Omron CX-Programmer project NewProject (CX-Programmer 8.10)

# PLC NewPLC1: CJ1M CPU11
I/O table (CPU CJ1M-CPU11): rack 0 slot 0 CJ1W-ID211; rack 0 slot 1 CJ1W-TC002

## Global symbols (name address type ; comment)
D2000 CHANNEL  ; Loop 1 Current Temperature To Touch Screen
D2001 CHANNEL  ; Loop 2 Current Temperature To Touch Screen
D2002 CHANNEL  ; Loop 3 Current Temperature To Touch Screen
D2003 CHANNEL  ; Loop 4 Current Temperature To Touch Screen
D2100 CHANNEL  ; Loop 1 Temperature Set Point From Touch Screen
D2101 CHANNEL  ; Loop 2 Temperature Set Point From Touch Screen
D2102 CHANNEL  ; Loop 3 Temperature Set Point From Touch Screen
D2103 CHANNEL  ; Loop 4 Temperature Set Point From Touch Screen
W0.00 BOOL  ; Loop 1 Set Point Button
W0.01 BOOL  ; Loop 2 Set Point Button
W0.02 BOOL  ; Loop 3 Set Point Button
W0.03 BOOL  ; Loop 4 Set Point Button
W1.00 BOOL  ; Loop 1 Autotune Start
W1.01 BOOL  ; Loop 2 Autotune Start
W1.02 BOOL  ; Loop 3 Autotune Start
W1.03 BOOL  ; Loop 4 Autotune Start
W2.00 BOOL  ; Loop 1 Autotuning In Progress
W2.01 BOOL  ; Loop 2 Autotuning In Progress
W2.02 BOOL  ; Loop 3 Autotuning In Progress
W2.03 BOOL  ; Loop 4 Autotuning In Progress
Loop1AL1Flag 2008.01 BOOL  ; $?St$Bk?_#[569] / Loop 1 AL1 Flag / The AL1/AL2 Flag is ON when the temperature is within the alarm range set for the input value. / The flag is OFF when the temperature is not within the alarm range set for the input value.$?St$Bk?_#[569]
Loop1AL2Flag 2008.00 BOOL  ; $?St$Bk?_#[570] / Loop 1 AL2 Flag / The AL1/AL2 Flag is ON when the temperature is within the alarm range set for the input value. / The flag is OFF when the temperature is not within the alarm range set for the input value.$?St$Bk?_#[570]
Loop1ATFlag 2008.03 BOOL  ; $?St$Bk?_#[571] / Loop 1 AT Flag / The AT Flag is ON when autotuning is being performed. / The AT Flag is OFF when autotuning is not being performed.$?St$Bk?_#[571]
Loop1ControlOutputFlag 2008.04 BOOL  ; $?St$Bk?_#[575] / Loop 1 Control Output Flag / The Control Output Flag is ON when the control output is ON.$?St$Bk?_#[575]
Loop1InputAlarm1SV D20030 CHANNEL  ; $?St$Bk?_#[577] / Loop 1 Input Alarm 1 SV / The Temperature Control Unit returns the values that are actually being used for temperature control. / Use these values to monitor operation.$?St$Bk?_#[577]
Loop1InputAlarm2SV D20031 CHANNEL  ; $?St$Bk?_#[578] / Loop 1 Input Alarm 2 SV / The Temperature Control Unit returns the values that are actually being used for temperature control. / Use these values to monitor operation.$?St$Bk?_#[578]
Loop1InputControlPeriod D20033 CHANNEL  ; $?St$Bk?_#[579] / Loop 1 Input Control Period / The Temperature Control Unit returns the values that are actually being used for temperature control. / Use these values to monitor operation.$?St$Bk?_#[579]
Loop1InputControlSensitivity D20034 CHANNEL  ; $?St$Bk?_#[580] / Loop 1 Input Control Sensitivity / The Temperature Control Unit returns the values that are actually being used for temperature control. / Use these values to monitor operation.$?St$Bk?_#[580]
Loop1InputDerivativeTime D20037 CHANNEL  ; $?St$Bk?_#[581] / Loop 1 Input Derivative Time / The Temperature Control Unit returns the values that are actually being used for temperature control. / Use these values to monitor operation.$?St$Bk?_#[581]
Loop1InputInputCompensationValue D20032 CHANNEL  ; $?St$Bk?_#[582] / Loop 1 Input Input Compensation Value / The Temperature Control Unit returns the values that are actually being used for temperature control. / Use these values to monitor operation.$?St$Bk?_#[582]
Loop1InputIntegralTime D20036 CHANNEL  ; $?St$Bk?_#[583] / Loop 1 Input Integral Time / The Temperature Control Unit returns the values that are actually being used for temperature control. / Use these values to monitor operation.$?St$Bk?_#[583]
Loop1InputProportionalBand D20035 CHANNEL  ; $?St$Bk?_#[585] / Loop 1 Input Proportional Band / The Temperature Control Unit returns the values that are actually being used for temperature control. / Use these values to monitor operation.$?St$Bk?_#[585]
Loop1OutputControlPeriod D20013 CHANNEL  ; $?St$Bk?_#[589] / Loop 1 Output Control Period / Set in 4-digit BCD or 16-bit binary. / The values written here are written to RAM.$?St$Bk?_#[589]
Loop1OutputControlSensitivity D20014 CHANNEL  ; $?St$Bk?_#[590] / Loop 1 Output Control Sensitivity / Set in 4-digit BCD or 16-bit binary. / The values written here are written to RAM. / This setting is valid with ON/OFF control only.$?St$Bk?_#[590]
Loop1OutputDerivativeTime D20017 CHANNEL  ; $?St$Bk?_#[591] / Loop 1 Output Derivative Time / Set in 4-digit BCD or 16-bit binary. / The values written here are not written to RAM while the PID Constants Calculated Flag is ON. / The values written here are written to RAM. / These settings are valid with PID control only$?St$Bk?_#[591]
Loop1OutputIntegralTime D20016 CHANNEL  ; $?St$Bk?_#[593] / Loop 1 Output Integral Time / Set in 4-digit BCD or 16-bit binary. / The values written here are not written to RAM while the PID Constants Calculated Flag is ON. / The values written here are written to RAM. / These settings are valid with PID control only$?St$Bk?_#[593]
Loop1OutputProportionalBand D20015 CHANNEL  ; $?St$Bk?_#[594] / Loop 1 Output Proportional Band / Set in 4-digit BCD or 16-bit binary. / The values written here are not written to RAM while the PID Constants Calculated Flag is ON. / The values written here are written to RAM. / These settings are valid with PID control only$?St$Bk?_#[594]
Loop1SaveBit 2002.15 BOOL  ; $?St$Bk?_#[597] / Loop 1 Save Bit / Operating Parameters are written from RAM to EEPROM in the Temperature Control Unit when a Save Bit is turned ON. Refer to 2-6 Data Ranges for a list of the specific parameters that are / written. / DO NOT turn OFF the power supply when data is being written / from RAM to EEPROM. Confirm that the Save Completed Flag / has turned ON before turning OFF the power supply.$?St$Bk?_#[597]
Loop1SensorErrorFlag 2008.14 BOOL  ; $?St$Bk?_#[599] / Loop 1 Sensor Error Flag / The Sensor Error Flag turns ON for the following: / A sensor is not connected. / The connection to sensor is broken. / A temperature exceeding the specified temperature range has been input.$?St$Bk?_#[599]
Loop1SettingErrorFlag 2008.09 BOOL  ; $?St$Bk?_#[602] / Loop 1 Setting Error Flag / The Setting Error Flag turns ON when there is a setting error in the settings in the I/O memory of the CPU Unit.$?St$Bk?_#[602]
Loop1StandbyFlag 2008.11 BOOL  ; $?St$Bk?_#[603] / Loop 1 Standby Flag / The Standby Flag turns ON when the Temperature Control Unit is waiting for I/O refreshing after power is turned ON or the Unit is restarted.$?St$Bk?_#[603]
Loop1StartATBit 2002.02 BOOL  ; $?St$Bk?_#[604] / Loop 1 Start AT Bit / Turn ON the Start AT Bit to start autotuning for loop 1. / The status / of the Stop AT Bit is ignored if the Stop AT Bit for loop 1 is ON.$?St$Bk?_#[604]
Loop1StopATBit 2002.03 BOOL  ; $?St$Bk?_#[605] / Loop 1 Stop AT Bit / Turn ON the Stop AT Bit to stop autotuning for loop 1. / The status of the Stop AT Bit is ignored if autotuning is not being performed.$?St$Bk?_#[605]
Loop1StopBit 2002.06 BOOL  ; $?St$Bk?_#[606] / Loop 1 Stop Bit / Turn OFF the Stop Bit to perform temperature control for loop 1 and turn it ON to stop temperature control for loop 1. / The Stop Bit will not function if pin 1 on the DIP switch is OFF and the CPU Unit is in PROGRAM mode.$?St$Bk?_#[606]
Loop2AL1Flag 2009.01 BOOL  ; $?St$Bk?_#[608] / Loop 2 AL1 Flag / The AL1/AL2 Flag is ON when the temperature is within the alarm range set for the input value. / The flag is OFF when the temperature is not within the alarm range set for the input value.$?St$Bk?_#[608]
Loop2AL2Flag 2009.00 BOOL  ; $?St$Bk?_#[609] / Loop 2 AL2 Flag / The AL1/AL2 Flag is ON when the temperature is within the alarm range set for the input value. / The flag is OFF when the temperature is not within the alarm range set for the input value.$?St$Bk?_#[609]
Loop2ATFlag 2009.03 BOOL  ; $?St$Bk?_#[610] / Loop 2 AT Flag / The AT Flag is ON when autotuning is being performed. / The AT Flag is OFF when autotuning is not being performed.$?St$Bk?_#[610]
Loop2ControlOutputFlag 2009.04 BOOL  ; $?St$Bk?_#[614] / Loop 2 Control Output Flag / The Control Output Flag is ON when the control output is ON.$?St$Bk?_#[614]
Loop2InputAlarm1SV D20040 CHANNEL  ; $?St$Bk?_#[616] / Loop 2 Input Alarm 1 SV / The Temperature Control Unit returns the values that are actually being used for temperature control. / Use these values to monitor operation.$?St$Bk?_#[616]
Loop2InputAlarm2SV D20041 CHANNEL  ; $?St$Bk?_#[617] / Loop 2 Input Alarm 2 SV / The Temperature Control Unit returns the values that are actually being used for temperature control. / Use these values to monitor operation.$?St$Bk?_#[617]
Loop2InputControlPeriod D20043 CHANNEL  ; $?St$Bk?_#[618] / Loop 2 Input Control Period / The Temperature Control Unit returns the values that are actually being used for temperature control. / Use these values to monitor operation.$?St$Bk?_#[618]
Loop2InputControlSensitivity D20044 CHANNEL  ; $?St$Bk?_#[619] / Loop 2 Input Control Sensitivity / The Temperature Control Unit returns the values that are actually being used for temperature control. / Use these values to monitor operation.$?St$Bk?_#[619]
Loop2InputDerivativeTime D20047 CHANNEL  ; $?St$Bk?_#[620] / Loop 2 Input Derivative Time / The Temperature Control Unit returns the values that are actually being used for temperature control. / Use these values to monitor operation.$?St$Bk?_#[620]
Loop2InputInputCompensationValue D20042 CHANNEL  ; $?St$Bk?_#[621] / Loop 2 Input Input Compensation Value / The Temperature Control Unit returns the values that are actually being used for temperature control. / Use these values to monitor operation.$?St$Bk?_#[621]
Loop2InputIntegralTime D20046 CHANNEL  ; $?St$Bk?_#[622] / Loop 2 Input Integral Time / The Temperature Control Unit returns the values that are actually being used for temperature control. / Use these values to monitor operation.$?St$Bk?_#[622]
Loop2InputProportionalBand D20045 CHANNEL  ; $?St$Bk?_#[624] / Loop 2 Input Proportional Band / The Temperature Control Unit returns the values that are actually being used for temperature control. / Use these values to monitor operation.$?St$Bk?_#[624]
Loop2OutputControlPeriod D20023 CHANNEL  ; $?St$Bk?_#[627] / Loop 2 Output Control Period / Set in 4-digit BCD or 16-bit binary. / The values written here are written to RAM.$?St$Bk?_#[627]
Loop2OutputControlSensitivity D20024 CHANNEL  ; $?St$Bk?_#[628] / Loop 2 Output Control Sensitivity / Set in 4-digit BCD or 16-bit binary. / The values written here are written to RAM. / This setting is valid with ON/OFF control only.$?St$Bk?_#[628]
Loop2OutputDerivativeTime D20027 CHANNEL  ; $?St$Bk?_#[629] / Loop 2 Output Derivative Time / Set in 4-digit BCD or 16-bit binary. / The values written here are not written to RAM while the PID Constants Calculated Flag is ON. / The values written here are written to RAM. / These settings are valid with PID control only$?St$Bk?_#[629]
Loop2OutputIntegralTime D20026 CHANNEL  ; $?St$Bk?_#[631] / Loop 2 Output Integral Time / Set in 4-digit BCD or 16-bit binary. / The values written here are not written to RAM while the PID Constants Calculated Flag is ON. / The values written here are written to RAM. / These settings are valid with PID control only$?St$Bk?_#[631]
Loop2OutputProportionalBand D20025 CHANNEL  ; $?St$Bk?_#[632] / Loop 2 Output Proportional Band / Set in 4-digit BCD or 16-bit binary. / The values written here are not written to RAM while the PID Constants Calculated Flag is ON. / The values written here are written to RAM. / These settings are valid with PID control only$?St$Bk?_#[632]
Loop2SaveBit 2002.14 BOOL  ; $?St$Bk?_#[635] / Loop 2 Save Bit / Operating Parameters are written from RAM to EEPROM in the Temperature Control Unit when a Save Bit is turned ON. Refer to 2-6 Data Ranges for a list of the specific parameters that are / written. / DO NOT turn OFF the power supply when data is being written / from RAM to EEPROM. Confirm that the Save Completed Flag / has turned ON before turning OFF the power supply.$?St$Bk?_#[635]
Loop2SensorErrorFlag 2009.14 BOOL  ; $?St$Bk?_#[637] / Loop 2 Sensor Error Flag / The Sensor Error Flag turns ON for the following: / A sensor is not connected. / The connection to sensor is broken. / A temperature exceeding the specified temperature range has been input.$?St$Bk?_#[637]
Loop2SettingErrorFlag 2009.09 BOOL  ; $?St$Bk?_#[640] / Loop 2 Setting Error Flag / The Setting Error Flag turns ON when there is a setting error in the settings in the I/O memory of the CPU Unit.$?St$Bk?_#[640]
Loop2StandbyFlag 2009.11 BOOL  ; $?St$Bk?_#[641] / Loop 2 Standby Flag / The Standby Flag turns ON when the Temperature Control Unit is waiting for I/O refreshing after power is turned ON or the Unit is restarted.$?St$Bk?_#[641]
Loop2StartATBit 2002.00 BOOL  ; $?St$Bk?_#[642] / Loop 2 Start AT Bit / Turn ON the Start AT Bit to start autotuning for loop 1. / The status / of the Stop AT Bit is ignored if the Stop AT Bit for loop 1 is ON.$?St$Bk?_#[642]
Loop2StopATBit 2002.01 BOOL  ; $?St$Bk?_#[643] / Loop 2 Stop AT Bit / Turn ON the Stop AT Bit to stop autotuning for loop 1. / The status of the Stop AT Bit is ignored if autotuning is not being performed.$?St$Bk?_#[643]
Loop2StopBit 2002.04 BOOL  ; $?St$Bk?_#[644] / Loop 2 Stop Bit / Turn OFF the Stop Bit to perform temperature control for loop 1 and turn it ON to stop temperature control for loop 1. / The Stop Bit will not function if pin 1 on the DIP switch is OFF and the CPU Unit is in PROGRAM mode.$?St$Bk?_#[644]
Loop3AL1Flag 2018.01 BOOL  ; $?St$Bk?_#[646] / Loop 3 AL1 Flag / The AL1/AL2 Flag is ON when the temperature is within the alarm range set for the input value. / The flag is OFF when the temperature is not within the alarm range set for the input value.$?St$Bk?_#[646]
Loop3AL2Flag 2018.00 BOOL  ; $?St$Bk?_#[647] / Loop 3 AL2 Flag / The AL1/AL2 Flag is ON when the temperature is within the alarm range set for the input value. / The flag is OFF when the temperature is not within the alarm range set for the input value.$?St$Bk?_#[647]
Loop3ATFlag 2018.03 BOOL  ; $?St$Bk?_#[648] / Loop 3 AT Flag / The AT Flag is ON when autotuning is being performed. / The AT Flag is OFF when autotuning is not being performed.$?St$Bk?_#[648]
Loop3ControlOutputFlag 2018.04 BOOL  ; $?St$Bk?_#[652] / Loop 3 Control Output Flag / The Control Output Flag is ON when the control output is ON.$?St$Bk?_#[652]
Loop3InputAlarm1SV D20070 CHANNEL  ; $?St$Bk?_#[654] / Loop 3 Input Alarm 1 SV / The Temperature Control Unit returns the values that are actually being used for temperature control. / Use these values to monitor operation.$?St$Bk?_#[654]
Loop3InputAlarm2SV D20071 CHANNEL  ; $?St$Bk?_#[655] / Loop 3 Input Alarm 2 SV / The Temperature Control Unit returns the values that are actually being used for temperature control. / Use these values to monitor operation.$?St$Bk?_#[655]
Loop3InputControlPeriod D20073 CHANNEL  ; $?St$Bk?_#[656] / Loop 3 Input Control Period / The Temperature Control Unit returns the values that are actually being used for temperature control. / Use these values to monitor operation.$?St$Bk?_#[656]
Loop3InputControlSensitivity D20074 CHANNEL  ; $?St$Bk?_#[657] / Loop 3 Input Control Sensitivity / The Temperature Control Unit returns the values that are actually being used for temperature control. / Use these values to monitor operation.$?St$Bk?_#[657]
Loop3InputDerivativeTime D20077 CHANNEL  ; $?St$Bk?_#[658] / Loop 3 Input Derivative Time / The Temperature Control Unit returns the values that are actually being used for temperature control. / Use these values to monitor operation.$?St$Bk?_#[658]
Loop3InputInputCompensationValue D20072 CHANNEL  ; $?St$Bk?_#[659] / Loop 3 Input Input Compensation Value / The Temperature Control Unit returns the values that are actually being used for temperature control. / Use these values to monitor operation.$?St$Bk?_#[659]
Loop3InputIntegralTime D20076 CHANNEL  ; $?St$Bk?_#[660] / Loop 3 Input Integral Time / The Temperature Control Unit returns the values that are actually being used for temperature control. / Use these values to monitor operation.$?St$Bk?_#[660]
Loop3InputProportionalBand D20075 CHANNEL  ; $?St$Bk?_#[662] / Loop 3 Input Proportional Band / The Temperature Control Unit returns the values that are actually being used for temperature control. / Use these values to monitor operation.$?St$Bk?_#[662]
Loop3OutputControlPeriod D20053 CHANNEL  ; $?St$Bk?_#[666] / Loop 3 Output Control Period / Set in 4-digit BCD or 16-bit binary. / The values written here are written to RAM.$?St$Bk?_#[666]
Loop3OutputControlSensitivity D20054 CHANNEL  ; $?St$Bk?_#[667] / Loop 3 Output Control Sensitivity / Set in 4-digit BCD or 16-bit binary. / The values written here are written to RAM. / This setting is valid with ON/OFF control only.$?St$Bk?_#[667]
Loop3OutputDerivativeTime D20057 CHANNEL  ; $?St$Bk?_#[668] / Loop 3 Output Derivative Time / Set in 4-digit BCD or 16-bit binary. / The values written here are not written to RAM while the PID Constants Calculated Flag is ON. / The values written here are written to RAM. / These settings are valid with PID control only$?St$Bk?_#[668]
Loop3OutputIntegralTime D20056 CHANNEL  ; $?St$Bk?_#[670] / Loop 3 Output Integral Time / Set in 4-digit BCD or 16-bit binary. / The values written here are not written to RAM while the PID Constants Calculated Flag is ON. / The values written here are written to RAM. / These settings are valid with PID control only$?St$Bk?_#[670]
Loop3OutputProportionalBand D20055 CHANNEL  ; $?St$Bk?_#[671] / Loop 3 Output Proportional Band / Set in 4-digit BCD or 16-bit binary. / The values written here are not written to RAM while the PID Constants Calculated Flag is ON. / The values written here are written to RAM. / These settings are valid with PID control only$?St$Bk?_#[671]
Loop3SaveBit 2012.15 BOOL  ; $?St$Bk?_#[674] / Loop 3 Save Bit / Operating Parameters are written from RAM to EEPROM in the Temperature Control Unit when a Save Bit is turned ON. Refer to 2-6 Data Ranges for a list of the specific parameters that are / written. / DO NOT turn OFF the power supply when data is being written / from RAM to EEPROM. Confirm that the Save Completed Flag / has turned ON before turning OFF the power supply.$?St$Bk?_#[674]
Loop3SensorErrorFlag 2018.14 BOOL  ; $?St$Bk?_#[676] / Loop 3 Sensor Error Flag / The Sensor Error Flag turns ON for the following: / A sensor is not connected. / The connection to sensor is broken. / A temperature exceeding the specified temperature range has been input.$?St$Bk?_#[676]
Loop3SettingErrorFlag 2018.09 BOOL  ; $?St$Bk?_#[679] / Loop 3 Setting Error Flag / The Setting Error Flag turns ON when there is a setting error in the settings in the I/O memory of the CPU Unit.$?St$Bk?_#[679]
Loop3StandbyFlag 2018.11 BOOL  ; $?St$Bk?_#[680] / Loop 3 Standby Flag / The Standby Flag turns ON when the Temperature Control Unit is waiting for I/O refreshing after power is turned ON or the Unit is restarted.$?St$Bk?_#[680]
Loop3StartATBit 2012.02 BOOL  ; $?St$Bk?_#[681] / Loop 3 Start AT Bit / Turn ON the Start AT Bit to start autotuning for Loop 3. / The status / of the Stop AT Bit is ignored if the Stop AT Bit for Loop 3 is ON.$?St$Bk?_#[681]
Loop3StopATBit 2012.03 BOOL  ; $?St$Bk?_#[682] / Loop 3 Stop AT Bit / Turn ON the Stop AT Bit to stop autotuning for Loop 3. / The status of the Stop AT Bit is ignored if autotuning is not being performed.$?St$Bk?_#[682]
Loop3StopBit 2012.06 BOOL  ; $?St$Bk?_#[683] / Loop 3 Stop Bit / Turn OFF the Stop Bit to perform temperature control for Loop 3 and turn it ON to stop temperature control for Loop 3. / The Stop Bit will not function if pin 1 on the DIP switch is OFF and the CPU Unit is in PROGRAM mode.$?St$Bk?_#[683]
Loop4AL1Flag 2019.01 BOOL  ; $?St$Bk?_#[685] / Loop 4 AL1 Flag / The AL1/AL2 Flag is ON when the temperature is within the alarm range set for the input value. / The flag is OFF when the temperature is not within the alarm range set for the input value.$?St$Bk?_#[685]
Loop4AL2Flag 2019.00 BOOL  ; $?St$Bk?_#[686] / Loop 4 AL2 Flag / The AL1/AL2 Flag is ON when the temperature is within the alarm range set for the input value. / The flag is OFF when the temperature is not within the alarm range set for the input value.$?St$Bk?_#[686]
Loop4ATFlag 2019.03 BOOL  ; $?St$Bk?_#[687] / Loop 4 AT Flag / The AT Flag is ON when autotuning is being performed. / The AT Flag is OFF when autotuning is not being performed.$?St$Bk?_#[687]
Loop4ControlOutputFlag 2019.04 BOOL  ; $?St$Bk?_#[691] / Loop 4 Control Output Flag / The Control Output Flag is ON when the control output is ON.$?St$Bk?_#[691]
Loop4InputAlarm1SV D20080 CHANNEL  ; $?St$Bk?_#[693] / Loop 4 Input Alarm 1 SV / The Temperature Control Unit returns the values that are actually being used for temperature control. / Use these values to monitor operation.$?St$Bk?_#[693]
Loop4InputAlarm2SV D20081 CHANNEL  ; $?St$Bk?_#[694] / Loop 4 Input Alarm 2 SV / The Temperature Control Unit returns the values that are actually being used for temperature control. / Use these values to monitor operation.$?St$Bk?_#[694]
Loop4InputControlPeriod D20083 CHANNEL  ; $?St$Bk?_#[695] / Loop 4 Input Control Period / The Temperature Control Unit returns the values that are actually being used for temperature control. / Use these values to monitor operation.$?St$Bk?_#[695]
Loop4InputControlSensitivity D20084 CHANNEL  ; $?St$Bk?_#[696] / Loop 4 Input Control Sensitivity / The Temperature Control Unit returns the values that are actually being used for temperature control. / Use these values to monitor operation.$?St$Bk?_#[696]
Loop4InputDerivativeTime D20087 CHANNEL  ; $?St$Bk?_#[697] / Loop 4 Input Derivative Time / The Temperature Control Unit returns the values that are actually being used for temperature control. / Use these values to monitor operation.$?St$Bk?_#[697]
Loop4InputInputCompensationValue D20082 CHANNEL  ; $?St$Bk?_#[698] / Loop 4 Input Input Compensation Value / The Temperature Control Unit returns the values that are actually being used for temperature control. / Use these values to monitor operation.$?St$Bk?_#[698]
Loop4InputIntegralTime D20086 CHANNEL  ; $?St$Bk?_#[699] / Loop 4 Input Integral Time / The Temperature Control Unit returns the values that are actually being used for temperature control. / Use these values to monitor operation.$?St$Bk?_#[699]
Loop4InputProportionalBand D20085 CHANNEL  ; $?St$Bk?_#[701] / Loop 4 Input Proportional Band / The Temperature Control Unit returns the values that are actually being used for temperature control. / Use these values to monitor operation.$?St$Bk?_#[701]
Loop4OutputControlPeriod D20063 CHANNEL  ; $?St$Bk?_#[704] / Loop 4 Output Control Period / Set in 4-digit BCD or 16-bit binary. / The values written here are written to RAM.$?St$Bk?_#[704]
Loop4OutputControlSensitivity D20064 CHANNEL  ; $?St$Bk?_#[705] / Loop 4 Output Control Sensitivity / Set in 4-digit BCD or 16-bit binary. / The values written here are written to RAM. / This setting is valid with ON/OFF control only.$?St$Bk?_#[705]
Loop4OutputDerivativeTime D20067 CHANNEL  ; $?St$Bk?_#[706] / Loop 4 Output Derivative Time / Set in 4-digit BCD or 16-bit binary. / The values written here are not written to RAM while the PID Constants Calculated Flag is ON. / The values written here are written to RAM. / These settings are valid with PID control only$?St$Bk?_#[706]
Loop4OutputIntegralTime D20066 CHANNEL  ; $?St$Bk?_#[708] / Loop 4 Output Integral Time / Set in 4-digit BCD or 16-bit binary. / The values written here are not written to RAM while the PID Constants Calculated Flag is ON. / The values written here are written to RAM. / These settings are valid with PID control only$?St$Bk?_#[708]
Loop4OutputProportionalBand D20065 CHANNEL  ; $?St$Bk?_#[709] / Loop 4 Output Proportional Band / Set in 4-digit BCD or 16-bit binary. / The values written here are not written to RAM while the PID Constants Calculated Flag is ON. / The values written here are written to RAM. / These settings are valid with PID control only$?St$Bk?_#[709]
Loop4SaveBit 2012.14 BOOL  ; $?St$Bk?_#[712] / Loop 4 Save Bit / Operating Parameters are written from RAM to EEPROM in the Temperature Control Unit when a Save Bit is turned ON. Refer to 2-6 Data Ranges for a list of the specific parameters that are / written. / DO NOT turn OFF the power supply when data is being written / from RAM to EEPROM. Confirm that the Save Completed Flag / has turned ON before turning OFF the power supply.$?St$Bk?_#[712]
Loop4SensorErrorFlag 2019.14 BOOL  ; $?St$Bk?_#[714] / Loop 4 Sensor Error Flag / The Sensor Error Flag turns ON for the following: / A sensor is not connected. / The connection to sensor is broken. / A temperature exceeding the specified temperature range has been input.$?St$Bk?_#[714]
Loop4SettingErrorFlag 2019.09 BOOL  ; $?St$Bk?_#[717] / Loop 4 Setting Error Flag / The Setting Error Flag turns ON when there is a setting error in the settings in the I/O memory of the CPU Unit.$?St$Bk?_#[717]
Loop4StandbyFlag 2019.11 BOOL  ; $?St$Bk?_#[718] / Loop 4 Standby Flag / The Standby Flag turns ON when the Temperature Control Unit is waiting for I/O refreshing after power is turned ON or the Unit is restarted.$?St$Bk?_#[718]
Loop4StartATBit 2012.00 BOOL  ; $?St$Bk?_#[719] / Loop 4 Start AT Bit / Turn ON the Start AT Bit to start autotuning for Loop 3. / The status / of the Stop AT Bit is ignored if the Stop AT Bit for Loop 3 is ON.$?St$Bk?_#[719]
Loop4StopATBit 2012.01 BOOL  ; $?St$Bk?_#[720] / Loop 4 Stop AT Bit / Turn ON the Stop AT Bit to stop autotuning for Loop 3. / The status of the Stop AT Bit is ignored if autotuning is not being performed.$?St$Bk?_#[720]
Loop4StopBit 2012.04 BOOL  ; $?St$Bk?_#[721] / Loop 4 Stop Bit / Turn OFF the Stop Bit to perform temperature control for Loop 3 and turn it ON to stop temperature control for Loop 3. / The Stop Bit will not function if pin 1 on the DIP switch is OFF and the CPU Unit is in PROGRAM mode.$?St$Bk?_#[721]

## Program NewProgram1 (cyclic task 0)

### Section ReadData

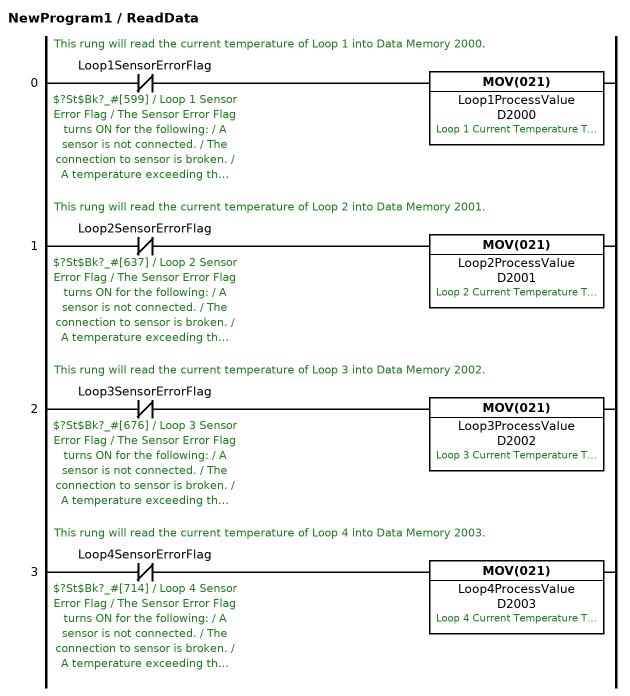
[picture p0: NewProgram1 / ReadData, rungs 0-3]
; rung 0: This rung will read the current temperature of Loop 1 into Data Memory 2000.
LDNOT Loop1SensorErrorFlag  ; $?St$Bk?_#[599] / Loop 1 Sensor Error Flag / The Sensor Error Flag turns ON for the following: / A sensor is not connected. / The connection to sensor is broken. / A temperature exceeding the specified temperature range has been input.$?St$Bk?_#[599]
MOV(021) Loop1ProcessValue D2000  ; Loop 1 Current Temperature To Touch Screen
; rung 1: This rung will read the current temperature of Loop 2 into Data Memory 2001.
LDNOT Loop2SensorErrorFlag  ; $?St$Bk?_#[637] / Loop 2 Sensor Error Flag / The Sensor Error Flag turns ON for the following: / A sensor is not connected. / The connection to sensor is broken. / A temperature exceeding the specified temperature range has been input.$?St$Bk?_#[637]
MOV(021) Loop2ProcessValue D2001  ; Loop 2 Current Temperature To Touch Screen
; rung 2: This rung will read the current temperature of Loop 3 into Data Memory 2002.
LDNOT Loop3SensorErrorFlag  ; $?St$Bk?_#[676] / Loop 3 Sensor Error Flag / The Sensor Error Flag turns ON for the following: / A sensor is not connected. / The connection to sensor is broken. / A temperature exceeding the specified temperature range has been input.$?St$Bk?_#[676]
MOV(021) Loop3ProcessValue D2002  ; Loop 3 Current Temperature To Touch Screen
; rung 3: This rung will read the current temperature of Loop 4 into Data Memory 2003.
LDNOT Loop4SensorErrorFlag  ; $?St$Bk?_#[714] / Loop 4 Sensor Error Flag / The Sensor Error Flag turns ON for the following: / A sensor is not connected. / The connection to sensor is broken. / A temperature exceeding the specified temperature range has been input.$?St$Bk?_#[714]
MOV(021) Loop4ProcessValue D2003  ; Loop 4 Current Temperature To Touch Screen

### Section WriteData

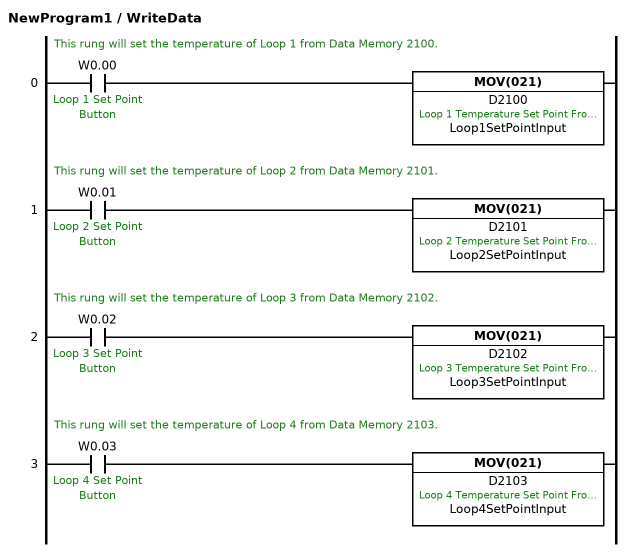
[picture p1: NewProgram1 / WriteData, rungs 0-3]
; rung 0: This rung will set the temperature of Loop 1 from Data Memory 2100.
LD W0.00  ; Loop 1 Set Point Button
MOV(021) D2100 Loop1SetPointInput  ; Loop 1 Temperature Set Point From Touch Screen
; rung 1: This rung will set the temperature of Loop 2 from Data Memory 2101.
LD W0.01  ; Loop 2 Set Point Button
MOV(021) D2101 Loop2SetPointInput  ; Loop 2 Temperature Set Point From Touch Screen
; rung 2: This rung will set the temperature of Loop 3 from Data Memory 2102.
LD W0.02  ; Loop 3 Set Point Button
MOV(021) D2102 Loop3SetPointInput  ; Loop 3 Temperature Set Point From Touch Screen
; rung 3: This rung will set the temperature of Loop 4 from Data Memory 2103.
LD W0.03  ; Loop 4 Set Point Button
MOV(021) D2103 Loop4SetPointInput  ; Loop 4 Temperature Set Point From Touch Screen

### Section Autotune

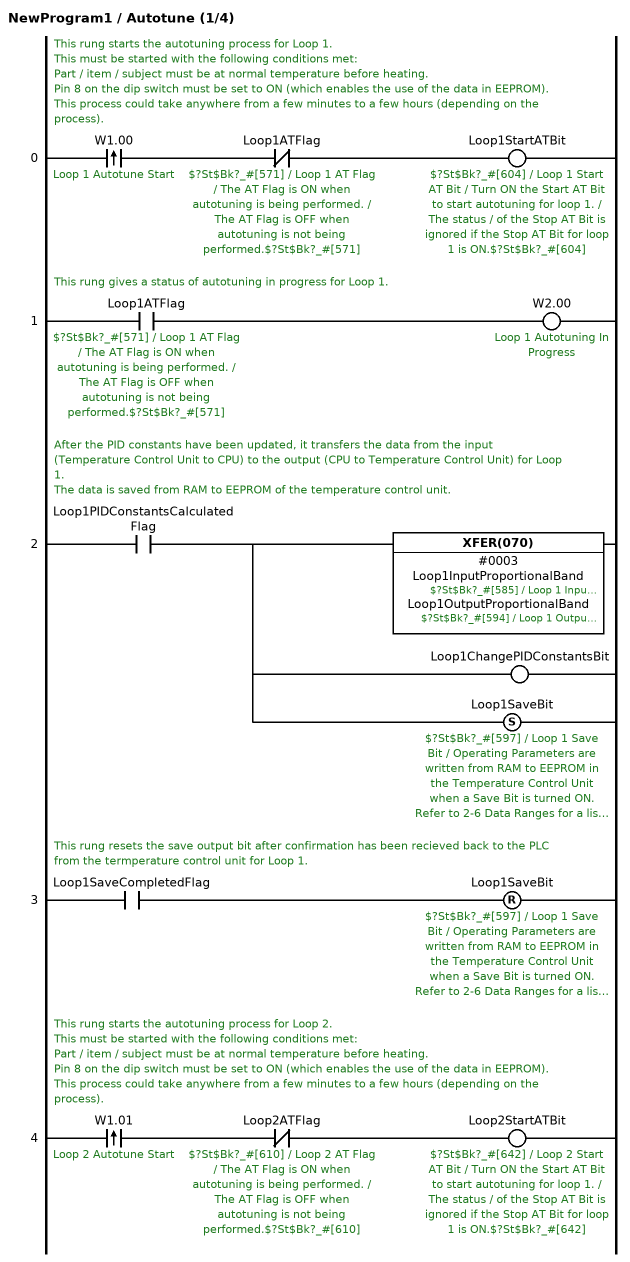
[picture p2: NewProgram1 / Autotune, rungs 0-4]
; rung 0: This rung starts the autotuning process for Loop 1. / This must be started with the following conditions met: / Part / item / subject must be at normal temperature before heating. / Pin 8 on the dip switch must be set to ON (which enables the use of the data in EEPROM). / This process could take anywhere from a few minutes to a few hours (depending on the process).
@LD W1.00  ; Loop 1 Autotune Start
ANDNOT Loop1ATFlag  ; $?St$Bk?_#[571] / Loop 1 AT Flag / The AT Flag is ON when autotuning is being performed. / The AT Flag is OFF when autotuning is not being performed.$?St$Bk?_#[571]
OUT Loop1StartATBit  ; $?St$Bk?_#[604] / Loop 1 Start AT Bit / Turn ON the Start AT Bit to start autotuning for loop 1. / The status / of the Stop AT Bit is ignored if the Stop AT Bit for loop 1 is ON.$?St$Bk?_#[604]
; rung 1: This rung gives a status of autotuning in progress for Loop 1.
LD Loop1ATFlag  ; $?St$Bk?_#[571] / Loop 1 AT Flag / The AT Flag is ON when autotuning is being performed. / The AT Flag is OFF when autotuning is not being performed.$?St$Bk?_#[571]
OUT W2.00  ; Loop 1 Autotuning In Progress
; rung 2: After the PID constants have been updated, it transfers the data from the input (Temperature Control Unit to CPU) to the output (CPU to Temperature Control Unit) for Loop 1. / The data is saved from RAM to EEPROM of the temperature control unit.
LD Loop1PIDConstantsCalculatedFlag
XFER(070) #0003 Loop1InputProportionalBand Loop1OutputProportionalBand  ; $?St$Bk?_#[585] / Loop 1 Input Proportional Band / The Temperature Control Unit returns the values that are actually being used for temperature control. / Use these values to monitor operation.$?St$Bk?_#[585], $?St$Bk?_#[594] / Loop 1 Output Proportional Band / Set in 4-digit BCD or 16-bit binary. / The values written here are not written to RAM while the PID Constants Calculated Flag is ON. / The values written here are written to RAM. / These settings are valid with PID control only$?St$Bk?_#[594]
OUT Loop1ChangePIDConstantsBit
SET Loop1SaveBit  ; $?St$Bk?_#[597] / Loop 1 Save Bit / Operating Parameters are written from RAM to EEPROM in the Temperature Control Unit when a Save Bit is turned ON. Refer to 2-6 Data Ranges for a list of the specific parameters that are / written. / DO NOT turn OFF the power supply when data is being written / from RAM to EEPROM. Confirm that the Save Completed Flag / has turned ON before turning OFF the power supply.$?St$Bk?_#[597]
; rung 3: This rung resets the save output bit after confirmation has been recieved back to the PLC from the termperature control unit for Loop 1.
LD Loop1SaveCompletedFlag
RSET Loop1SaveBit  ; $?St$Bk?_#[597] / Loop 1 Save Bit / Operating Parameters are written from RAM to EEPROM in the Temperature Control Unit when a Save Bit is turned ON. Refer to 2-6 Data Ranges for a list of the specific parameters that are / written. / DO NOT turn OFF the power supply when data is being written / from RAM to EEPROM. Confirm that the Save Completed Flag / has turned ON before turning OFF the power supply.$?St$Bk?_#[597]
; rung 4: This rung starts the autotuning process for Loop 2. / This must be started with the following conditions met: / Part / item / subject must be at normal temperature before heating. / Pin 8 on the dip switch must be set to ON (which enables the use of the data in EEPROM). / This process could take anywhere from a few minutes to a few hours (depending on the process).
@LD W1.01  ; Loop 2 Autotune Start
ANDNOT Loop2ATFlag  ; $?St$Bk?_#[610] / Loop 2 AT Flag / The AT Flag is ON when autotuning is being performed. / The AT Flag is OFF when autotuning is not being performed.$?St$Bk?_#[610]
OUT Loop2StartATBit  ; $?St$Bk?_#[642] / Loop 2 Start AT Bit / Turn ON the Start AT Bit to start autotuning for loop 1. / The status / of the Stop AT Bit is ignored if the Stop AT Bit for loop 1 is ON.$?St$Bk?_#[642]

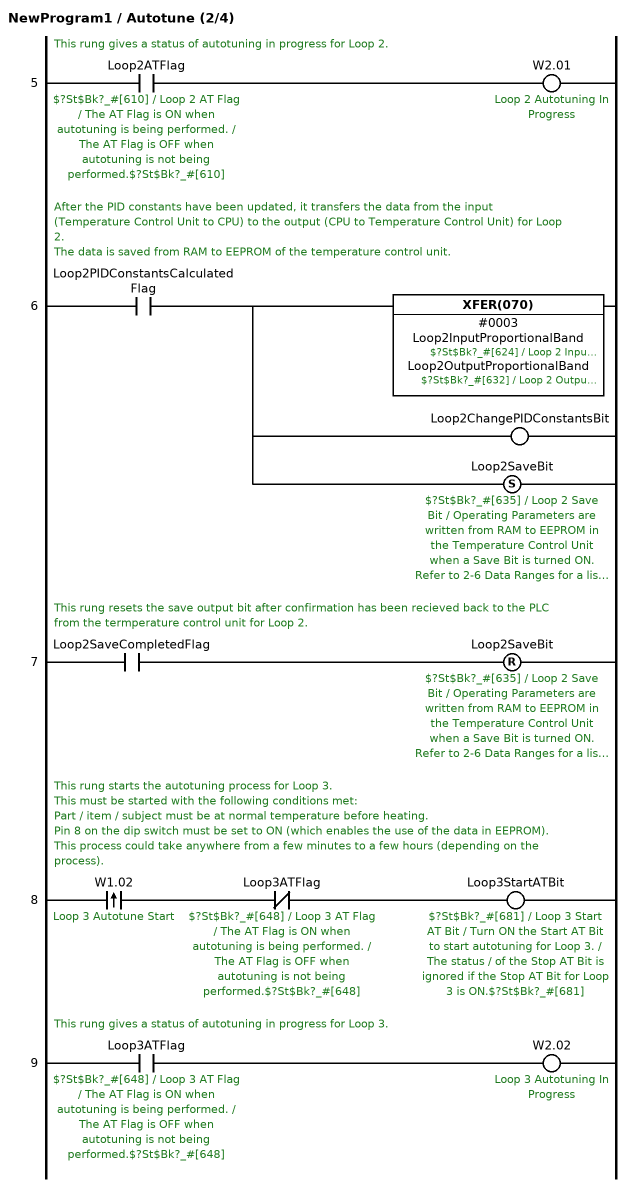
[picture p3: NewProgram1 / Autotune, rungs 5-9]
; rung 5: This rung gives a status of autotuning in progress for Loop 2.
LD Loop2ATFlag  ; $?St$Bk?_#[610] / Loop 2 AT Flag / The AT Flag is ON when autotuning is being performed. / The AT Flag is OFF when autotuning is not being performed.$?St$Bk?_#[610]
OUT W2.01  ; Loop 2 Autotuning In Progress
; rung 6: After the PID constants have been updated, it transfers the data from the input (Temperature Control Unit to CPU) to the output (CPU to Temperature Control Unit) for Loop 2. / The data is saved from RAM to EEPROM of the temperature control unit.
LD Loop2PIDConstantsCalculatedFlag
XFER(070) #0003 Loop2InputProportionalBand Loop2OutputProportionalBand  ; $?St$Bk?_#[624] / Loop 2 Input Proportional Band / The Temperature Control Unit returns the values that are actually being used for temperature control. / Use these values to monitor operation.$?St$Bk?_#[624], $?St$Bk?_#[632] / Loop 2 Output Proportional Band / Set in 4-digit BCD or 16-bit binary. / The values written here are not written to RAM while the PID Constants Calculated Flag is ON. / The values written here are written to RAM. / These settings are valid with PID control only$?St$Bk?_#[632]
OUT Loop2ChangePIDConstantsBit
SET Loop2SaveBit  ; $?St$Bk?_#[635] / Loop 2 Save Bit / Operating Parameters are written from RAM to EEPROM in the Temperature Control Unit when a Save Bit is turned ON. Refer to 2-6 Data Ranges for a list of the specific parameters that are / written. / DO NOT turn OFF the power supply when data is being written / from RAM to EEPROM. Confirm that the Save Completed Flag / has turned ON before turning OFF the power supply.$?St$Bk?_#[635]
; rung 7: This rung resets the save output bit after confirmation has been recieved back to the PLC from the termperature control unit for Loop 2.
LD Loop2SaveCompletedFlag
RSET Loop2SaveBit  ; $?St$Bk?_#[635] / Loop 2 Save Bit / Operating Parameters are written from RAM to EEPROM in the Temperature Control Unit when a Save Bit is turned ON. Refer to 2-6 Data Ranges for a list of the specific parameters that are / written. / DO NOT turn OFF the power supply when data is being written / from RAM to EEPROM. Confirm that the Save Completed Flag / has turned ON before turning OFF the power supply.$?St$Bk?_#[635]
; rung 8: This rung starts the autotuning process for Loop 3. / This must be started with the following conditions met: / Part / item / subject must be at normal temperature before heating. / Pin 8 on the dip switch must be set to ON (which enables the use of the data in EEPROM). / This process could take anywhere from a few minutes to a few hours (depending on the process).
@LD W1.02  ; Loop 3 Autotune Start
ANDNOT Loop3ATFlag  ; $?St$Bk?_#[648] / Loop 3 AT Flag / The AT Flag is ON when autotuning is being performed. / The AT Flag is OFF when autotuning is not being performed.$?St$Bk?_#[648]
OUT Loop3StartATBit  ; $?St$Bk?_#[681] / Loop 3 Start AT Bit / Turn ON the Start AT Bit to start autotuning for Loop 3. / The status / of the Stop AT Bit is ignored if the Stop AT Bit for Loop 3 is ON.$?St$Bk?_#[681]
; rung 9: This rung gives a status of autotuning in progress for Loop 3.
LD Loop3ATFlag  ; $?St$Bk?_#[648] / Loop 3 AT Flag / The AT Flag is ON when autotuning is being performed. / The AT Flag is OFF when autotuning is not being performed.$?St$Bk?_#[648]
OUT W2.02  ; Loop 3 Autotuning In Progress

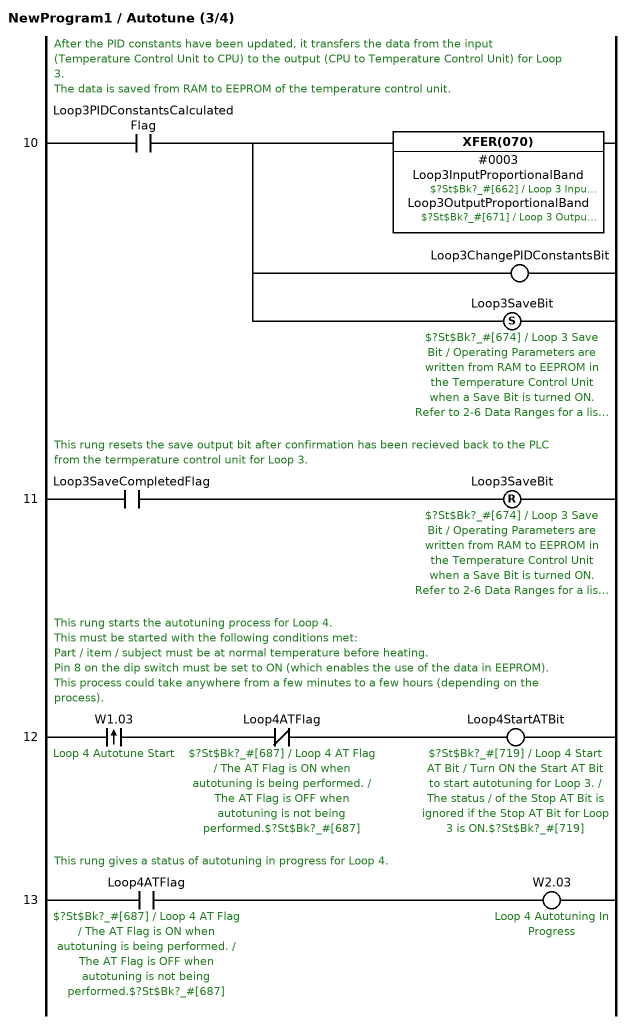
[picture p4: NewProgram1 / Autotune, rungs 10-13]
; rung 10: After the PID constants have been updated, it transfers the data from the input (Temperature Control Unit to CPU) to the output (CPU to Temperature Control Unit) for Loop 3. / The data is saved from RAM to EEPROM of the temperature control unit.
LD Loop3PIDConstantsCalculatedFlag
XFER(070) #0003 Loop3InputProportionalBand Loop3OutputProportionalBand  ; $?St$Bk?_#[662] / Loop 3 Input Proportional Band / The Temperature Control Unit returns the values that are actually being used for temperature control. / Use these values to monitor operation.$?St$Bk?_#[662], $?St$Bk?_#[671] / Loop 3 Output Proportional Band / Set in 4-digit BCD or 16-bit binary. / The values written here are not written to RAM while the PID Constants Calculated Flag is ON. / The values written here are written to RAM. / These settings are valid with PID control only$?St$Bk?_#[671]
OUT Loop3ChangePIDConstantsBit
SET Loop3SaveBit  ; $?St$Bk?_#[674] / Loop 3 Save Bit / Operating Parameters are written from RAM to EEPROM in the Temperature Control Unit when a Save Bit is turned ON. Refer to 2-6 Data Ranges for a list of the specific parameters that are / written. / DO NOT turn OFF the power supply when data is being written / from RAM to EEPROM. Confirm that the Save Completed Flag / has turned ON before turning OFF the power supply.$?St$Bk?_#[674]
; rung 11: This rung resets the save output bit after confirmation has been recieved back to the PLC from the termperature control unit for Loop 3.
LD Loop3SaveCompletedFlag
RSET Loop3SaveBit  ; $?St$Bk?_#[674] / Loop 3 Save Bit / Operating Parameters are written from RAM to EEPROM in the Temperature Control Unit when a Save Bit is turned ON. Refer to 2-6 Data Ranges for a list of the specific parameters that are / written. / DO NOT turn OFF the power supply when data is being written / from RAM to EEPROM. Confirm that the Save Completed Flag / has turned ON before turning OFF the power supply.$?St$Bk?_#[674]
; rung 12: This rung starts the autotuning process for Loop 4. / This must be started with the following conditions met: / Part / item / subject must be at normal temperature before heating. / Pin 8 on the dip switch must be set to ON (which enables the use of the data in EEPROM). / This process could take anywhere from a few minutes to a few hours (depending on the process).
@LD W1.03  ; Loop 4 Autotune Start
ANDNOT Loop4ATFlag  ; $?St$Bk?_#[687] / Loop 4 AT Flag / The AT Flag is ON when autotuning is being performed. / The AT Flag is OFF when autotuning is not being performed.$?St$Bk?_#[687]
OUT Loop4StartATBit  ; $?St$Bk?_#[719] / Loop 4 Start AT Bit / Turn ON the Start AT Bit to start autotuning for Loop 3. / The status / of the Stop AT Bit is ignored if the Stop AT Bit for Loop 3 is ON.$?St$Bk?_#[719]
; rung 13: This rung gives a status of autotuning in progress for Loop 4.
LD Loop4ATFlag  ; $?St$Bk?_#[687] / Loop 4 AT Flag / The AT Flag is ON when autotuning is being performed. / The AT Flag is OFF when autotuning is not being performed.$?St$Bk?_#[687]
OUT W2.03  ; Loop 4 Autotuning In Progress

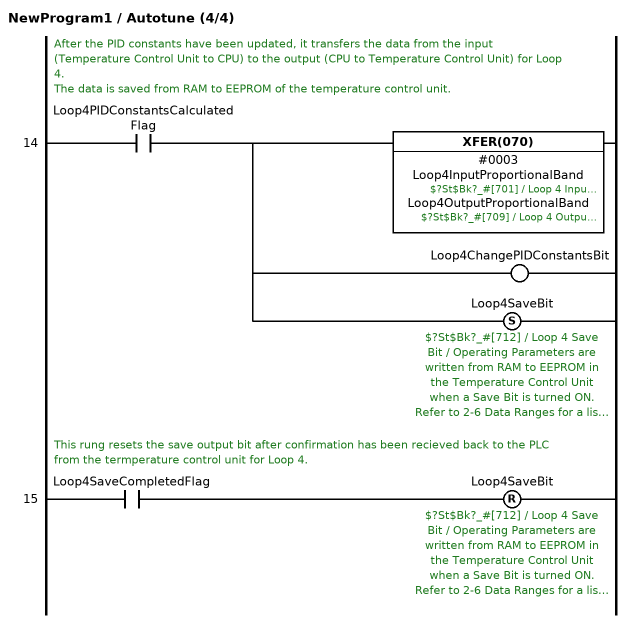
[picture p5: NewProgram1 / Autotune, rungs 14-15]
; rung 14: After the PID constants have been updated, it transfers the data from the input (Temperature Control Unit to CPU) to the output (CPU to Temperature Control Unit) for Loop 4. / The data is saved from RAM to EEPROM of the temperature control unit.
LD Loop4PIDConstantsCalculatedFlag
XFER(070) #0003 Loop4InputProportionalBand Loop4OutputProportionalBand  ; $?St$Bk?_#[701] / Loop 4 Input Proportional Band / The Temperature Control Unit returns the values that are actually being used for temperature control. / Use these values to monitor operation.$?St$Bk?_#[701], $?St$Bk?_#[709] / Loop 4 Output Proportional Band / Set in 4-digit BCD or 16-bit binary. / The values written here are not written to RAM while the PID Constants Calculated Flag is ON. / The values written here are written to RAM. / These settings are valid with PID control only$?St$Bk?_#[709]
OUT Loop4ChangePIDConstantsBit
SET Loop4SaveBit  ; $?St$Bk?_#[712] / Loop 4 Save Bit / Operating Parameters are written from RAM to EEPROM in the Temperature Control Unit when a Save Bit is turned ON. Refer to 2-6 Data Ranges for a list of the specific parameters that are / written. / DO NOT turn OFF the power supply when data is being written / from RAM to EEPROM. Confirm that the Save Completed Flag / has turned ON before turning OFF the power supply.$?St$Bk?_#[712]
; rung 15: This rung resets the save output bit after confirmation has been recieved back to the PLC from the termperature control unit for Loop 4.
LD Loop4SaveCompletedFlag
RSET Loop4SaveBit  ; $?St$Bk?_#[712] / Loop 4 Save Bit / Operating Parameters are written from RAM to EEPROM in the Temperature Control Unit when a Save Bit is turned ON. Refer to 2-6 Data Ranges for a list of the specific parameters that are / written. / DO NOT turn OFF the power supply when data is being written / from RAM to EEPROM. Confirm that the Save Completed Flag / has turned ON before turning OFF the power supply.$?St$Bk?_#[712]

### Section END
; rung 0
END(001)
